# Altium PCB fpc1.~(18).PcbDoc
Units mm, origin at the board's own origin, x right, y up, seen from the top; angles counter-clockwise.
Board outline 89.5 x 7.33 mm, 2 copper layers (Top Layer, Bottom Layer), stack 0.049 mm thick; 5 components, 5 nets, 20 pads, 4 vias.
Unrouted connection lines stored in the file: 4.
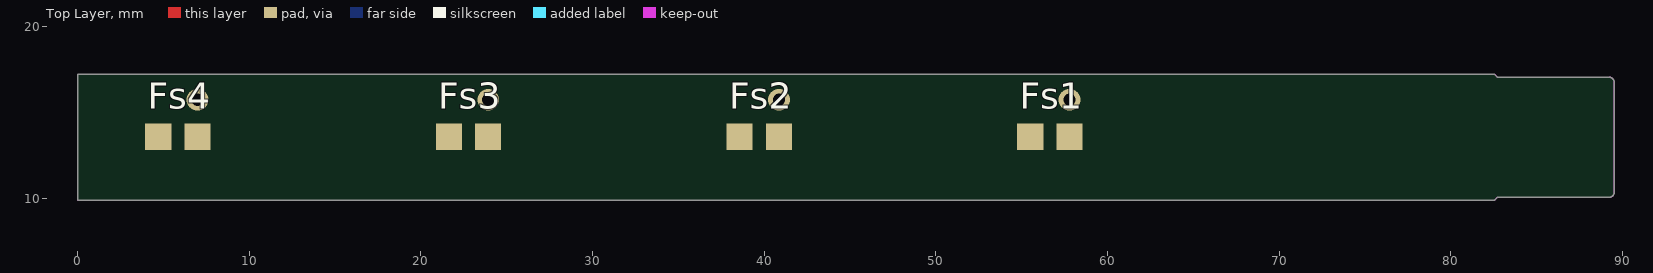
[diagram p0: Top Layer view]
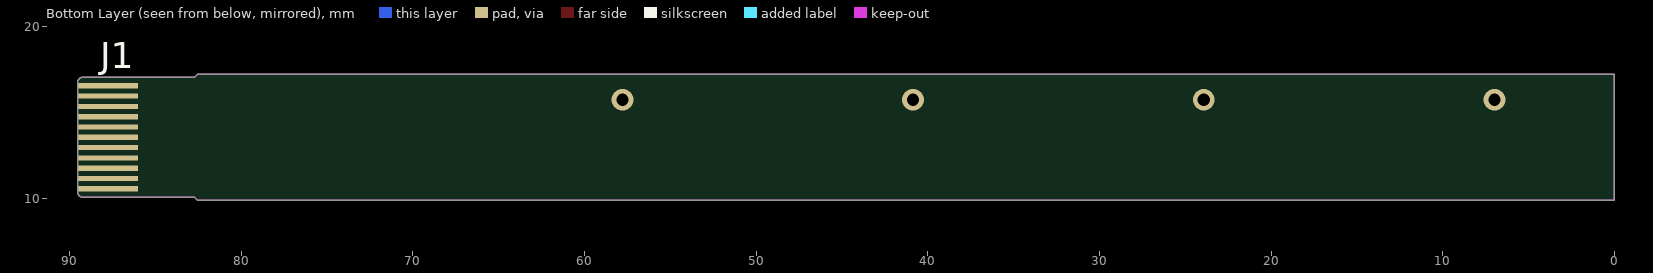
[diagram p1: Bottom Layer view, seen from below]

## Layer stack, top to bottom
Top Solder: solder mask 0.0102, Solder Resist, Dk 3.5
Top Layer: signal copper 0.012
Dielectric 1: dielectric 0.025, FR-4, Dk 4.8
Bottom Layer: signal copper 0.012
Bottom Solder: solder mask 0.0102, Solder Resist, Dk 3.5

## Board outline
0.013,9.893 0.013,17.225 82.547,17.225 82.713,17.059 89.213,17.059 cw(c89.213,16.759) 89.513,16.759 89.513,10.359 cw(c89.213,10.359) 89.213,10.059 82.713,10.059 82.547,9.893

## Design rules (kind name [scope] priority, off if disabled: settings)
Clearance [All] p1: gap=0.254 ignorepadtopadclearanceinfootprint=FALSE except(0: Arc-Hole Track-Hole SMDPad-Hole THPad-Hole Via-Hole Fill-Hole Poly-Hole Region-Hole Text-Hole; 0.2: SMDPad-SMDPad SMDPad-THPad SMDPad-Via SMDPad-Fill SMDPad-Poly SMDPad-Region SMDPad-Text)
DiffPairsRouting [All] p1: maxlimit=0.254 minlimit=0.254 mostfreqgap=0.254 toplayer_minwidth=0.381 toplayer_maxwidth=0.381 toplayer_prefwidth=0.381 bottomlayer_minwidth=0.381 bottomlayer_maxwidth=0.381 bottomlayer_prefwidth=0.381 substack1={6BAC4FC8-8DE6-4E41-AF8A-9441F3E19743} toplayer_{6bac4fc8-8de6-4e41-af8a-9441f3e19743}_minwidth=0.381 toplayer_{6bac4fc8-8de6-4e41-af8a-9441f3e19743}_maxwidth=0.381 toplayer_{6bac4fc8-8de6-4e41-af8a-9441f3e19743}_prefwidth=0.381 bottomlayer_{6bac4fc8-8de6-4e41-af8a-9441f3e19743}_minwidth=0.381 bottomlayer_{6bac4fc8-8de6-4e41-af8a-9441f3e19743}_maxwidth=0.381 bottomlayer_{6bac4fc8-8de6-4e41-af8a-9441f3e19743}_prefwidth=0.381 maxuncoupledlength=12.7
PolygonConnect [All] p1: connectstyle=Relief reliefconductorwidth=0.254 reliefentries=4 polygonreliefangle="90 Angle" airgapwidth=0.254
RoutingVias [All] p1: holewidth=0.711 width=1.27 viastyle="Through Hole" minholewidth=0.711 minwidth=1.27 maxholewidth=0.711 maxwidth=1.27
SolderMaskExpansion [All] p1: expansion=0.102 istentingtop=FALSE
Width [All] p1: maxlimit=0.254 minlimit=0.254 preferedwidth=0.254 substack1={6BAC4FC8-8DE6-4E41-AF8A-9441F3E19743}
29 further rules are at their usual default settings.

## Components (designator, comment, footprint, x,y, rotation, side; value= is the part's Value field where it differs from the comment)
Fs1 "ForceSensor" sensor_connector 56.642,13.589 r0 top
Fs2 "ForceSensor" sensor_connector 39.709,13.589 r0 top
Fs3 "ForceSensor" sensor_connector 22.775,13.589 r0 top
Fs4 "ForceSensor" sensor_connector 5.842,13.589 r0 top
J1 "FPC_connector" FPC_connector 87.75,13.559 r180 bottom

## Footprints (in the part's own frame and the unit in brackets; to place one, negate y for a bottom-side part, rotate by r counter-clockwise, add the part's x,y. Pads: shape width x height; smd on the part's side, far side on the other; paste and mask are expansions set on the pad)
FPC_connector [mm]
  rect 3.5x0.3 smd: 0(0,3) 1(0,3) 2(0,2.4) 3(0,1.8) 4(0,1.2) 5(0,0.6) 6(0,0) 7(0,-0.6) 8(0,-1.2) 9(0,-1.8) 10(0,-2.4) 11(0,-3)
sensor_connector [mil]
  rect 60x60 smd: 1(-45,0) 2(45,0)

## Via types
v1: diameter 1.27, hole 0.711, Top Layer to Bottom Layer, 4 vias

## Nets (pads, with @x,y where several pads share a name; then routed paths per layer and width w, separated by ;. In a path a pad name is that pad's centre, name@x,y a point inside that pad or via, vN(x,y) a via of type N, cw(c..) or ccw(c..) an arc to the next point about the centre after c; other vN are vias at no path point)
FS1: J1.1
FS2: J1.2
FS3: J1.3
FS4: J1.4
GND: Fs1.1 Fs2.1 Fs3.1 Fs4.1 J1.0
pads on no net: Fs1.2 Fs2.2 Fs3.2 Fs4.2 J1.5 J1.6 J1.7 J1.8 J1.9 J1.10 J1.11
copper on no net:
  other v1: 6.985,15.748 23.918,15.748 40.852,15.748 57.785,15.748

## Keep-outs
Keep-Out Layer:
  the board outline again, w0.013

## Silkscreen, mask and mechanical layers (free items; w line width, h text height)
Board Shape:
  the board outline again, w0.013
